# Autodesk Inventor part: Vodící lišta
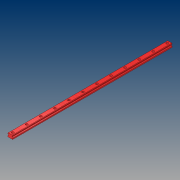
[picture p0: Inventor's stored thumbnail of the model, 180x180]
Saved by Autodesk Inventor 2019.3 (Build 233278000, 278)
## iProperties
Created: 2019-01
Part Number: Vodící lišta
Material: Ocel, uhlík
Document SubType Name: Modeling
Designer: B-hon
Density: 7.85 g/cm^3
Appearance: Světle červená
Author: B-hon
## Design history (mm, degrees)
sketch "Náčrt1"
  geometry: L1 (-10, 0)-(0, 0); L2 (0, 15.5)-(-8.5, 15.5); L3 (-7, 7.5)-(-10, 4.5); L4 (-7, 7.5)-(-2.445, 7.5); L5 (0, 15.408)-(0, -3.325) reference; L6 (-7, 7.5)-(-7, 9); L7 (-7, 9)-(-10, 12); L8 (-10, 14)-(-8.5, 15.5); L9 (-10, 14)-(-10, 12); L10 (-10, 4.5)-(-10, 0); L11 (0, 15.5)-(8.5, 15.5); L12 (10, 14)-(8.5, 15.5); L13 (10, 14)-(10, 12); L14 (7, 9)-(10, 12); L15 (7, 7.5)-(7, 9); L16 (7, 7.5)-(10, 4.5); L17 (10, 4.5)-(10, 0); L18 (10, 0)-(0, 0); 3 further points
  constraints: 36 end point, 7 symmetric about line, 3 point on line, 3 vertical, 2 horizontal, 2 perpendicular, 1 coincident, 1 midpoint, 1 parallel, 1 vertical alignment
  dimensions: "d1" = 15.5 distance of point (-10, 15.5) L1.start; "d3" = 135 deg angle of L3 L4; "d4" = 7 distance from line of L5 L3.start; "d5" = 7.5 distance from line of L1 L3.start; "d6" = 1.5 distance of L3.start L6.end; "d12" = 10 distance of L1.start L1.end; "d13" = 90 deg angle of L3 L7; "d14" = 1.5 distance of point (-10, 15.5) L8.start; "d15" = 1.5 distance from line of L2.end L9 (= d14)
extrude "Vysunutí1" new body sketch "Náčrt1" distance "d9" = 680; taper "d10" = 0 deg
sketch "Náčrt3"
  geometry: L1 (17, 680)-(0, 680) reference; L2 (0, 680)-(0, 0) reference; 2 further points
  dimensions: "d16" = 10 distance from line of L1 point (8.5, 670); "d17" = 8.5 distance from line of L2 point (8.5, 670)
hole "Díra1" sketch "Náčrt3" at (8.5, 670) diameter "d18" = 6; stored, may be unused: countersink angle "d22" = 90 deg, drill point angle "d24" = 118 deg; dims "d19" = 12, "d20" = 9.5, "d21" = 8, "d23" = 8
pattern_linear "Obdélníkové pole1" dims "d27" = 60
node "Těleso1"
other parameters: "d0" = 15, "d2" = 7.5 (= 0.5 x d0), "d7" = 1.5
